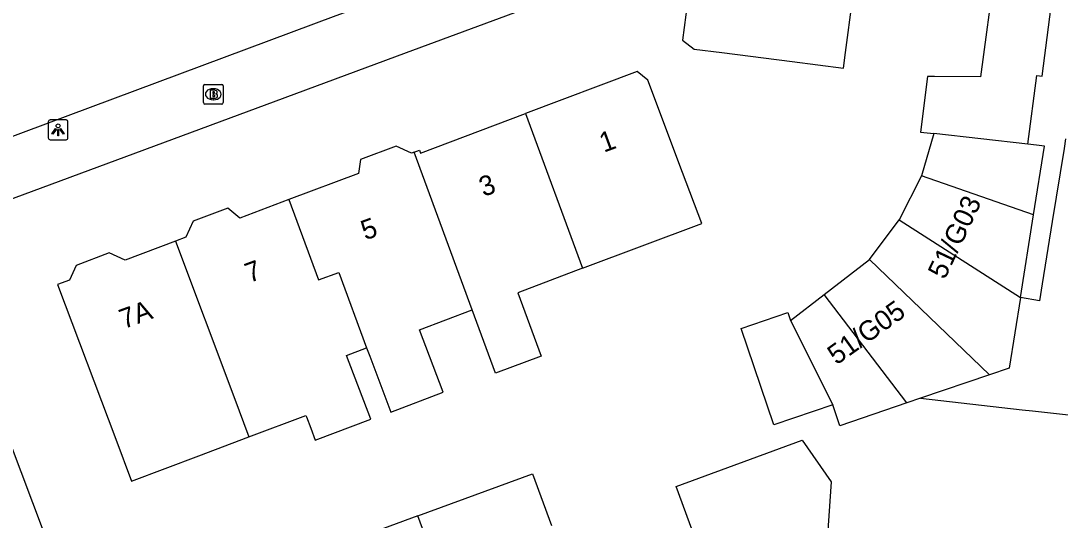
# Model space of a CAD drawing. Extents: x 161258 to 161838, y 380836 to 381727.
# Drawn here: x 161708.3 to 161760.9, y 381476.3 to 381501.6 of the extents above; entities that cross this region are included whole.
import ezdxf

# ---------------------------------------------------------------- set-up
doc = ezdxf.new("R2010")
doc.units = 0
for name, color, linetype in [('IMGEO_Brandkraan', 7, 'Continuous'), ('IMGEO_Lichtpunt', 7, 'Continuous'), ('IMGEO_Pand', 7, 'Continuous'), ('IMGEO_Pand_nummerreeks', 7, 'Continuous'), ('IMGEO_Rijbaan_lokaal_open', 7, 'Continuous'), ('IMGEO_Voetpad_open', 7, 'Continuous')]:
    doc.layers.add(name, color=color, linetype=linetype)

msp = doc.modelspace()

# ---------------------------------------------------------------- linework, layer by layer
at = {"layer": 'IMGEO_Brandkraan'}
for p, q in [((161717.512, 381497.464), (161717.512, 381498.316)), ((161717.587, 381498.39), (161718.439, 381498.39)), ((161718, 381498.17), (161718.025, 381498.17)), ((161718.513, 381498.316), (161718.513, 381497.464)), ((161718.023, 381497.61), (161717.998, 381497.61)), ((161718.439, 381497.39), (161717.587, 381497.39))]:
    msp.add_line(p, q, dxfattribs=at)
for points in [[(161717.512, 381497.464), (161717.512, 381498.316)], [(161717.587, 381498.39), (161718.439, 381498.39)], [(161717.86, 381498.09), (161717.86, 381497.69), (161718.073, 381497.69)], [(161718.091, 381498.09), (161717.86, 381498.09)], [(161718.039, 381498.009), (161717.985, 381498.009), (161717.985, 381497.933)], [(161718.513, 381498.316), (161718.513, 381497.464)], [(161717.985, 381497.933), (161718.038, 381497.933)], [(161718.047, 381497.857), (161717.985, 381497.857), (161717.985, 381497.776)], [(161717.985, 381497.776), (161718.047, 381497.776)], [(161718.439, 381497.39), (161717.587, 381497.39)]]:
    msp.add_lwpolyline(points, dxfattribs=at)
for centre, radius, start, end in [((161717.589, 381498.314), 0.0765, 91.552, 178.448), ((161717.589, 381498.314), 0.0765, 91.552, 178.448), ((161718.04, 381497.971), 0.0379, 267.8285, 90.9355), ((161718.095, 381497.945), 0.145, 59.4692, 91.5367), ((161718.12, 381497.992), 0.0922, 285.5137, 58.1501), ((161718.437, 381498.314), 0.0765, 1.552, 88.448), ((161718.437, 381498.314), 0.0765, 1.552, 88.448), ((161717.589, 381497.466), 0.0765, 181.552, 268.448), ((161717.589, 381497.466), 0.0765, 181.552, 268.448), ((161718.048, 381497.816), 0.0404, 269.8759, 90.5077), ((161718.079, 381497.941), 0.251, 268.6676, 293.5347), ((161718.125, 381497.8), 0.105, 301.3115, 78.989), ((161718.437, 381497.466), 0.0765, 271.552, 358.448), ((161718.437, 381497.466), 0.0765, 271.552, 358.448)]:
    msp.add_arc(centre, radius, start, end, dxfattribs=at)
for centre, major_axis, ratio, start_param, end_param in [((161717.999, 381497.89), (-0.387, 0.002), 0.722429, 4.712389, 7.853982), ((161718.024, 381497.89), (-0.39, 0.002), 0.717154, 1.570796, 4.712389)]:
    msp.add_ellipse(centre, major_axis=major_axis, ratio=ratio, start_param=start_param, end_param=end_param, dxfattribs=at)
at = {"layer": 'IMGEO_Lichtpunt'}
for p, q in [((161709.66, 381496.491), (161709.66, 381495.684)), ((161709.66, 381496.491), (161709.66, 381495.684)), ((161710.562, 381496.586), (161709.754, 381496.586)), ((161710.562, 381496.586), (161709.754, 381496.586)), ((161710.656, 381495.684), (161710.656, 381496.491)), ((161710.656, 381495.684), (161710.656, 381496.491)), ((161709.754, 381495.59), (161710.562, 381495.59)), ((161709.754, 381495.59), (161710.562, 381495.59))]:
    msp.add_line(p, q, dxfattribs=at)
for points in [[(161710.034, 381496.155), (161710.073, 381496.127), (161709.885, 381495.865), (161709.847, 381495.892), (161710.034, 381496.155)], [(161710.136, 381496.107), (161710.183, 381496.107), (161710.183, 381495.785), (161710.136, 381495.785), (161710.136, 381496.107)], [(161710.246, 381496.127), (161710.284, 381496.154), (161710.471, 381495.892), (161710.432, 381495.864), (161710.246, 381496.127)]]:
    msp.add_lwpolyline(points, dxfattribs=at)
msp.add_circle((161710.159, 381496.289), 0.0994, dxfattribs=at)
for centre, start, end in [((161709.754, 381496.491), 90, 180), ((161709.754, 381496.491), 90, 180), ((161710.562, 381496.491), 0, 90), ((161710.562, 381496.491), 0, 90), ((161709.754, 381495.684), 180, 270), ((161709.754, 381495.684), 180, 270), ((161710.562, 381495.684), 270, 0), ((161710.562, 381495.684), 270, 360)]:
    msp.add_arc(centre, 0.0946, start, end, dxfattribs=at)
at = {"layer": 'IMGEO_Pand'}
for points in [[(161742.513, 381506.415), (161741.751, 381500.632), (161742.344, 381500.177), (161743.749, 381500), (161747.305, 381499.552), (161749.906, 381499.217), (161750.009, 381500), (161750.709, 381505.346)], [(161759.231, 381495.368), (161759.684, 381498.836), (161759.952, 381498.806), (161760.603, 381503.785), (161757.562, 381504.185), (161756.831, 381498.777), (161754.515, 381498.795), (161754.156, 381498.796), (161753.809, 381495.975), (161754.477, 381495.9)], [(161736.7, 381489.079), (161742.73, 381491.352), (161741.758, 381493.931), (161739.995, 381498.609), (161739.465, 381499.043), (161733.82, 381496.915)], [(161728.179, 381494.958), (161728.442, 381495.057), (161728.497, 381494.909), (161733.82, 381496.915)], [(161733.82, 381496.915), (161736.7, 381489.079)], [(161754.477, 381495.9), (161753.846, 381493.767)], [(161759.231, 381495.368), (161754.477, 381495.9)], [(161761.143, 381495.628), (161761.066, 381495.148), (161760.473, 381491.447), (161759.967, 381488.294), (161759.83, 381487.438), (161758.855, 381487.594)], [(161759.526, 381491.778), (161760.085, 381495.268), (161759.68, 381495.318), (161759.231, 381495.368)], [(161728.179, 381494.958), (161728.051, 381494.91), (161727.272, 381495.263), (161725.469, 381494.583), (161725.354, 381493.881), (161721.842, 381492.557)], [(161731.114, 381486.973), (161728.179, 381494.958)], [(161753.809, 381482.497), (161758.946, 381481.922), (161759.47, 381481.864), (161763.567, 381481.405), (161764.588, 381487.772), (161765.764, 381495.111)], [(161753.846, 381493.767), (161752.73, 381491.526)], [(161759.526, 381491.778), (161753.846, 381493.767)], [(161721.842, 381492.557), (161719.361, 381491.622), (161718.746, 381492.126), (161716.996, 381491.467), (161716.625, 381490.647), (161716.094, 381490.447)], [(161721.842, 381492.557), (161723.336, 381488.491), (161724.371, 381488.871), (161725.773, 381485.046)], [(161758.855, 381487.594), (161759.526, 381491.778)], [(161751.217, 381489.527), (161752.73, 381491.526)], [(161752.73, 381491.526), (161758.855, 381487.594)], [(161716.094, 381490.447), (161713.558, 381489.49), (161712.744, 381489.859), (161711.068, 381489.227), (161710.729, 381488.479), (161710.123, 381488.262), (161713.078, 381480.425), (161713.876, 381478.308), (161717.276, 381479.59), (161719.806, 381480.544)], [(161716.094, 381490.447), (161719.053, 381482.593), (161719.806, 381480.544)], [(161748.923, 381487.757), (161751.217, 381489.527)], [(161757.286, 381483.678), (161751.217, 381489.527)], [(161736.7, 381489.079), (161733.423, 381487.844), (161734.606, 381484.625), (161732.29, 381483.773), (161731.114, 381486.973)], [(161747.216, 381486.44), (161748.923, 381487.757)], [(161753.115, 381482.261), (161748.923, 381487.757)], [(161758.855, 381487.594), (161758.282, 381484.016), (161757.286, 381483.678)], [(161725.773, 381485.046), (161725.932, 381484.623), (161726.996, 381481.802), (161729.647, 381482.802), (161728.452, 381485.97), (161731.114, 381486.973)], [(161749.359, 381482.171), (161746.387, 381481.161), (161744.73, 381486.037), (161747.081, 381486.836), (161747.216, 381486.44)], [(161747.216, 381486.44), (161749.359, 381482.171)], [(161719.806, 381480.544), (161722.697, 381481.634), (161722.726, 381481.558), (161722.941, 381480.986), (161723.171, 381480.377), (161725.978, 381481.435), (161724.761, 381484.665), (161725.773, 381485.046)], [(161757.286, 381483.678), (161753.809, 381482.497)], [(161753.115, 381482.261), (161749.72, 381481.107), (161749.359, 381482.171)], [(161753.809, 381482.497), (161753.115, 381482.261)], [(161744.734, 381471.827), (161743.649, 381472.01), (161741.438, 381478.04), (161747.81, 381480.376), (161749.286, 381478.266), (161748.793, 381471.156)], [(161728.371, 381476.549), (161734.167, 381478.674), (161735.127, 381476.056)], [(161728.371, 381476.549), (161725.214, 381475.391), (161726.174, 381472.774)], [(161729.333, 381473.932), (161728.371, 381476.549)]]:
    msp.add_lwpolyline(points, dxfattribs=at)
at = {"layer": 'IMGEO_Rijbaan_lokaal_open'}
msp.add_lwpolyline([(161729.353, 381503.742), (161729.019, 381503.62), (161724.209, 381501.861), (161701.588, 381493.419)], dxfattribs=at)
at = {"layer": 'IMGEO_Voetpad_open'}
for points in [[(161703.642, 381491.064), (161721.654, 381497.729), (161727.792, 381500), (161733.594, 381502.147)], [(161711.187, 381471.057), (161703.642, 381491.064)]]:
    msp.add_lwpolyline(points, dxfattribs=at)

# ---------------------------------------------------------------- texts
at = {"layer": 'IMGEO_Pand_nummerreeks'}
for s, rotation, p in [('1', 20.2132, (161737.777, 381494.928)), ('3', 20.2132, (161731.689, 381492.687)), ('51/G03', 64.6526, (161755.031, 381488.471)), ('5', 20.2132, (161725.707, 381490.485)), ('7', 20.1624, (161719.84, 381488.329)), ('51/G05', 35.5348, (161749.554, 381484.158)), ('7A', 20.0967, (161713.48, 381485.998))]:
    msp.add_text(s, height=1, rotation=rotation, dxfattribs=at).set_placement(p)

doc.saveas('drawing.dxf')
